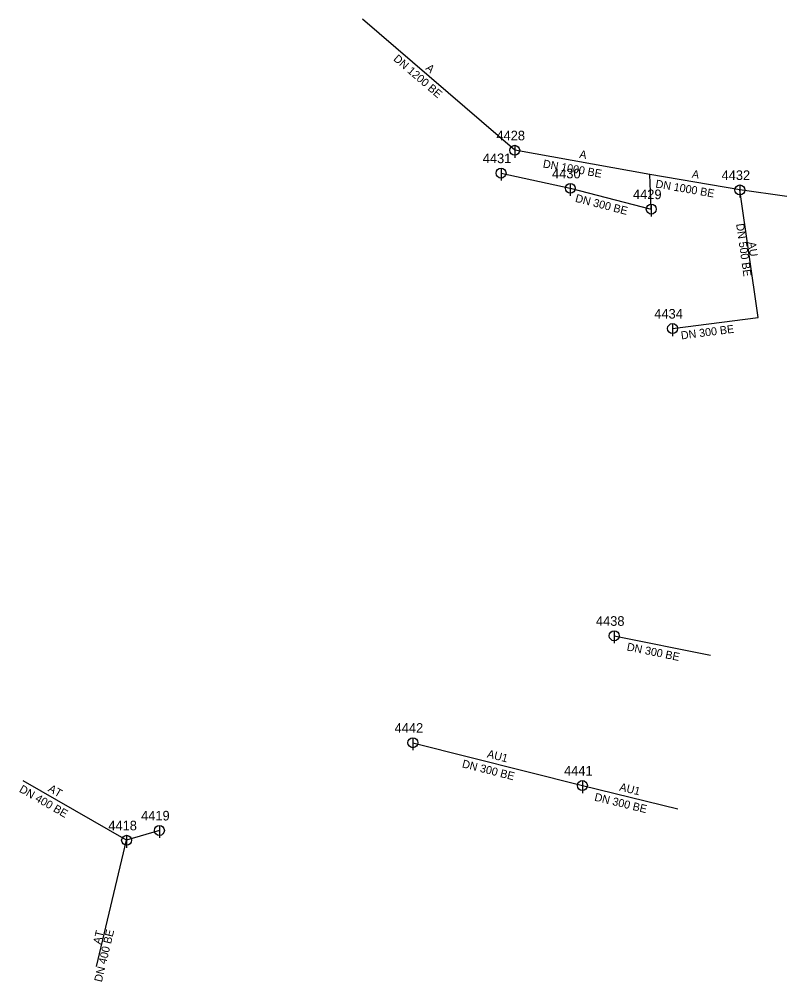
# Model space of a CAD drawing. Extents: x -467410 to -467256, y -1120336 to -1120143.
import ezdxf

# ---------------------------------------------------------------- set-up
doc = ezdxf.new("R2010")
doc.units = 0
for name, color, linetype in [('_stoka_jednotna_smvak_prevzato_z_dokumentace_', 7, 'Continuous'), ('Default', 7, 'Continuous'), ('MoLevel 119', 7, 'Continuous'), ('MoLevel 120', 7, 'Continuous'), ('MoLevel 68', 7, 'Continuous'), ('MoLevel 69', 7, 'Continuous')]:
    doc.layers.add(name, color=color, linetype=linetype)

# ---------------------------------------------------------------- blocks, each defined once
blk = doc.blocks.new('_sachta_kanal_prevzato_z_dokumentace_')
at = {"layer": 'Default'}
blk.add_line((0, 0.05), (0, -0.075), dxfattribs=at)
blk.add_circle((0, 0), 0.05, dxfattribs=at)

msp = doc.modelspace()

# ---------------------------------------------------------------- linework, layer by layer
at = {"layer": '_stoka_jednotna_smvak_prevzato_z_dokumentace_'}
for p, q in [((-467310.46, -1120169.05), (-467340.97, -1120142.76)), ((-467283.34, -1120173.89), (-467310.46, -1120169.05)), ((-467313.2, -1120173.63), (-467299.31, -1120176.68)), ((-467265.32, -1120177.01), (-467283.34, -1120173.89)), ((-467283.08, -1120180.85), (-467283.34, -1120173.89)), ((-467299.31, -1120176.68), (-467283.08, -1120180.85)), ((-467255.92, -1120178.35), (-467265.32, -1120177.01)), ((-467261.66, -1120202.62), (-467265.32, -1120177.01)), ((-467278.81, -1120204.81), (-467261.66, -1120202.62)), ((-467290.51, -1120266.44), (-467271.18, -1120270.36)), ((-467330.87, -1120287.89), (-467296.9, -1120296.48)), ((-467388.27, -1120307.47), (-467409, -1120295.55)), ((-467296.9, -1120296.48), (-467277.79, -1120301.14)), ((-467381.7, -1120305.49), (-467388.27, -1120307.47)), ((-467394.31, -1120332.75), (-467388.27, -1120307.47))]:
    msp.add_line(p, q, dxfattribs=at)

# ---------------------------------------------------------------- block references
at = {"layer": 'MoLevel 119', "xscale": 20, "yscale": 20}
for p in [(-467310.46, -1120169.05), (-467313.2, -1120173.63), (-467299.31, -1120176.68), (-467265.32, -1120177.01), (-467283.08, -1120180.85), (-467278.81, -1120204.81), (-467290.51, -1120266.44), (-467330.87, -1120287.89), (-467296.9, -1120296.48), (-467381.7, -1120305.49), (-467388.27, -1120307.47)]:
    msp.add_blockref('_sachta_kanal_prevzato_z_dokumentace_', p, dxfattribs=at)

# ---------------------------------------------------------------- texts
at = {"layer": 'MoLevel 120'}
for s, p in [('4428', (-467314.13, -1120167.05)), ('4431', (-467316.87, -1120171.63)), ('4430', (-467302.98, -1120174.68)), ('4432', (-467268.99, -1120175.01)), ('4429', (-467286.75, -1120178.85)), ('4434', (-467282.48, -1120202.81)), ('4438', (-467294.18, -1120264.44)), ('4442', (-467334.54, -1120285.89)), ('4441', (-467300.57, -1120294.48)), ('4419', (-467385.37, -1120303.49)), ('4418', (-467391.94, -1120305.47))]:
    msp.add_text(s, height=1.926, dxfattribs=at).set_placement(p)
at = {"layer": 'MoLevel 68'}
for s, rotation, p in [('DN 1200 BE', 319.2475, (-467334.91, -1120150.9)), ('DN 1000 BE', 349.8767, (-467304.89, -1120172.47)), ('DN 1000 BE', 350.1973, (-467282.32, -1120176.5)), ('DN 300 BE', 345.5906, (-467298.44, -1120179.36)), ('DN 500 BE', 278.1304, (-467266.08, -1120183.84)), ('DN 300 BE', 7.2833, (-467277.04, -1120207)), ('DN 300 BE', 348.5323, (-467288.09, -1120269.37)), ('DN 300 BE', 345.8091, (-467321.13, -1120292.81)), ('DN 400 BE', 330.1048, (-467409.95, -1120297.66)), ('DN 300 BE', 346.2954, (-467294.59, -1120299.49)), ('DN 400 BE', 76.5672, (-467393.25, -1120336.01))]:
    msp.add_text(s, height=1.605, rotation=rotation, dxfattribs=at).set_placement(p)
at = {"layer": 'MoLevel 69'}
for s, height, rotation, p in [('A', 1.6, 319.2475, (-467328.45, -1120152.75)), ('A', 1.6, 349.8767, (-467297.58, -1120170.55)), ('A', 1.6, 350.1973, (-467275.01, -1120174.53)), ('AU', 1.605, 278.1304, (-467263.7, -1120187.5)), ('AU1', 1.605, 345.8091, (-467316.11, -1120290.82)), ('AT', 1.605, 330.1048, (-467404.15, -1120297.54)), ('AU1', 1.605, 346.2954, (-467289.57, -1120297.47)), ('AT', 1.605, 76.5672, (-467393.47, -1120328.43))]:
    msp.add_text(s, height=height, rotation=rotation, dxfattribs=at).set_placement(p)

doc.saveas('drawing.dxf')
